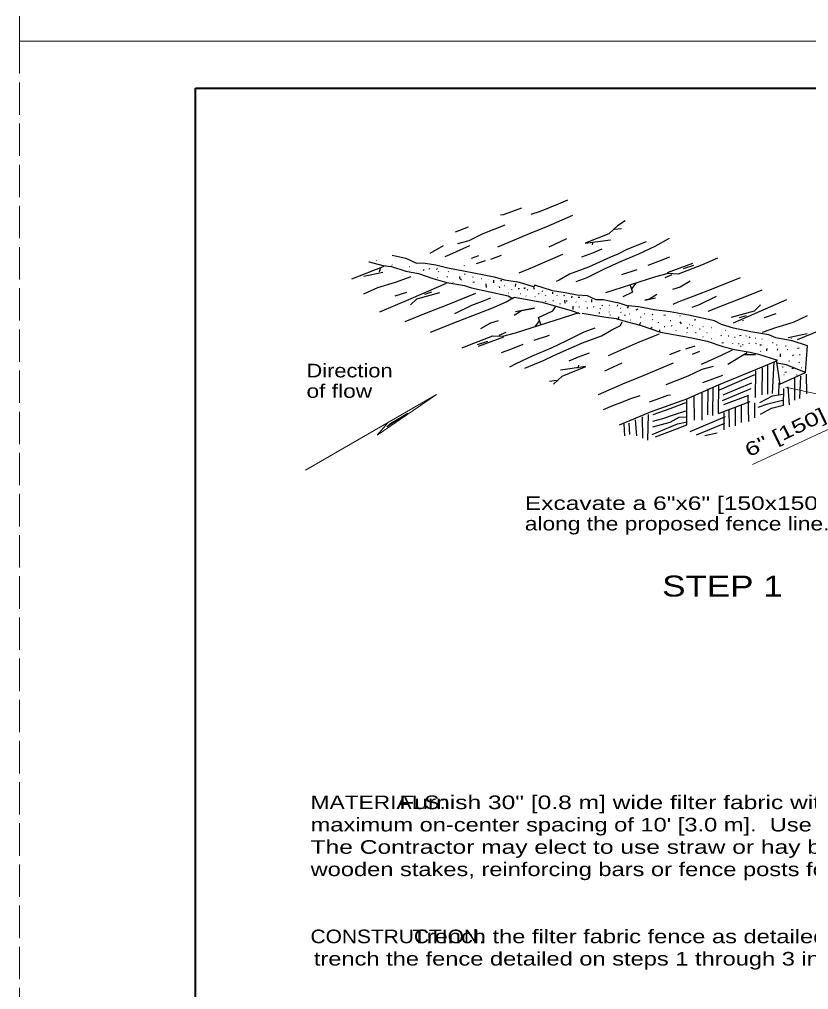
# Model space of a CAD drawing. Extents: x 1083.1 to 1117.1, y 672.5 to 716.5.
# Drawn here: x 1083.13 to 1092.18, y 683.63 to 694.76 of the extents above; entities that cross this region are included whole.
import ezdxf

# ---------------------------------------------------------------- set-up
doc = ezdxf.new("R2010")
doc.units = 0
doc.header["$LTSCALE"] = 0.062
doc.linetypes.add('LONG_DASHED', pattern=[7.5, 6, -1.5])
doc.layers.add('1', color=7, linetype='Continuous', lineweight=13)

msp = doc.modelspace()

# ---------------------------------------------------------------- linework, layer by layer
at = {"layer": '1', "lineweight": 25}
for p, q in [((1085.14617, 693.96842), (1116.64617, 693.96842)), ((1085.14617, 672.96842), (1085.14617, 693.96842)), ((1088.27583, 692.37417), (1088.12517, 692.31983)), ((1090.03117, 692.35733), (1089.95358, 692.34725)), ((1089.40017, 692.24183), (1089.198, 692.14725)), ((1089.69883, 692.17333), (1089.70692, 692.20775)), ((1087.9885, 692.16242), (1087.83625, 692.07217)), ((1087.13633, 691.97783), (1087.14017, 691.97783)), ((1087.21825, 691.98925), (1087.22358, 691.995)), ((1087.40317, 692.05483), (1087.56, 692.0205)), ((1087.98525, 691.98033), (1087.98525, 691.98242)), ((1088.39283, 692.04892), (1088.30775, 692.01483)), ((1088.47092, 691.98842), (1088.36717, 691.95633)), ((1088.65175, 692.05267), (1088.53117, 692.0035)), ((1086.941, 691.78267), (1087.30975, 691.929)), ((1087.25858, 691.8655), (1087.272, 691.91433)), ((1087.39858, 691.94333), (1087.40125, 691.9405)), ((1087.60042, 691.92325), (1087.60583, 691.92617)), ((1087.68383, 691.86875), (1087.68658, 691.86875)), ((1087.7565, 691.87733), (1087.77, 691.88883)), ((1087.91267, 691.88883), (1087.92342, 691.90317)), ((1087.938, 691.86133), (1087.93258, 691.86708)), ((1088.05267, 691.86133), (1088.04725, 691.86708)), ((1088.23025, 691.9315), (1088.2305, 691.93492)), ((1090.20925, 691.88833), (1090.03283, 691.83067)), ((1090.84667, 691.95858), (1090.55733, 691.85067)), ((1090.85917, 691.93817), (1090.74075, 691.89792)), ((1087.29358, 691.85725), (1087.07825, 691.81133)), ((1087.92733, 691.79383), (1087.92192, 691.79958)), ((1088.03667, 691.80383), (1088.03125, 691.80958)), ((1088.23933, 691.83383), (1088.23392, 691.83958)), ((1088.33258, 691.79883), (1088.32725, 691.80458)), ((1088.42133, 691.7855), (1088.42675, 691.7855)), ((1088.50208, 691.77117), (1088.50475, 691.77117)), ((1088.56942, 691.73675), (1088.56667, 691.76825)), ((1088.646, 691.76258), (1088.6595, 691.76258)), ((1090.60908, 691.83067), (1090.52917, 691.7955)), ((1088.10333, 691.73633), (1088.09792, 691.74208)), ((1088.23292, 691.708), (1088.3135, 691.6795)), ((1088.32717, 691.74533), (1088.34867, 691.74817)), ((1088.48325, 691.68508), (1088.48058, 691.72525)), ((1088.54783, 691.67358), (1088.55058, 691.67358)), ((1088.63133, 691.6965), (1088.634, 691.67933)), ((1088.6905, 691.70517), (1088.69317, 691.70517)), ((1088.77667, 691.65925), (1088.77392, 691.665)), ((1088.817, 691.6965), (1088.81967, 691.72525)), ((1088.84658, 691.67358), (1088.86275, 691.67358)), ((1088.95808, 691.654), (1088.95275, 691.65975)), ((1089.03358, 691.66208), (1089.0255, 691.68225)), ((1089.12875, 691.6365), (1089.12333, 691.64225)), ((1090.197, 691.73433), (1090.14592, 691.66833)), ((1087.43625, 691.5875), (1087.57083, 691.6305)), ((1087.85342, 691.63017), (1087.77267, 691.60433)), ((1088.73358, 691.62192), (1088.73625, 691.62475)), ((1088.8735, 691.61042), (1088.87083, 691.61042)), ((1088.93942, 691.584), (1088.93408, 691.58975)), ((1089.04433, 691.576), (1089.039, 691.576)), ((1089.08742, 691.61042), (1089.07933, 691.61042)), ((1089.16608, 691.589), (1089.16067, 691.59475)), ((1089.24625, 691.61042), (1089.2435, 691.63058)), ((1089.25158, 691.53008), (1089.2435, 691.53008)), ((1089.29942, 691.589), (1089.294, 691.59475)), ((1089.37542, 691.59033), (1089.37808, 691.60183)), ((1089.38617, 691.50425), (1089.3835, 691.53867)), ((1089.39967, 691.53008), (1089.41042, 691.533)), ((1089.55575, 691.57025), (1089.53425, 691.57025)), ((1089.693, 691.51575), (1089.693, 691.54733)), ((1090.29875, 691.53875), (1090.42325, 691.56475)), ((1089.16608, 691.5215), (1089.16067, 691.52725)), ((1089.33142, 691.4915), (1089.326, 691.49725)), ((1089.48042, 691.4325), (1089.48042, 691.46983)), ((1089.51267, 691.51575), (1089.51, 691.51858)), ((1089.54233, 691.46408), (1089.55308, 691.46408)), ((1089.62842, 691.52433), (1089.62575, 691.5215)), ((1089.63383, 691.45258), (1089.64725, 691.45258)), ((1089.70917, 691.46692), (1089.71725, 691.46408)), ((1089.814, 691.474), (1089.80858, 691.47975)), ((1089.89667, 691.4765), (1089.89125, 691.48225)), ((1090.12267, 691.46675), (1089.98267, 691.51267)), ((1089.98642, 691.46983), (1089.99183, 691.487)), ((1090.02142, 691.44683), (1090.02408, 691.44683)), ((1090.11292, 691.44683), (1090.10217, 691.46408)), ((1090.20175, 691.42967), (1090.22325, 691.44108)), ((1089.78458, 691.38658), (1089.7765, 691.39808)), ((1089.89492, 691.40092), (1089.89492, 691.40383)), ((1089.90733, 691.364), (1089.90192, 691.36967)), ((1089.99717, 691.31483), (1090.00258, 691.34925)), ((1090.03, 691.394), (1090.02458, 691.39967)), ((1090.06983, 691.37225), (1090.06717, 691.36075)), ((1090.12908, 691.378), (1090.12642, 691.378)), ((1090.13175, 691.31483), (1090.13717, 691.31483)), ((1090.25558, 691.34067), (1090.25558, 691.34642)), ((1090.29867, 691.38658), (1090.30133, 691.38658)), ((1090.3955, 691.37225), (1090.38475, 691.37508)), ((1090.39017, 691.31483), (1090.39283, 691.32058)), ((1090.51708, 691.36758), (1090.53592, 691.3705)), ((1090.71142, 691.35158), (1090.706, 691.35733)), ((1091.10083, 691.30325), (1090.80208, 691.36642)), ((1090.86642, 691.31508), (1090.88525, 691.318)), ((1091.38667, 691.33825), (1091.46742, 691.36408)), ((1091.42917, 691.30325), (1091.42883, 691.31067)), ((1091.80383, 691.38092), (1091.66933, 691.33792)), ((1089.04308, 691.23408), (1089.09425, 691.30008)), ((1090.23408, 691.24883), (1090.25558, 691.28608)), ((1090.36592, 691.21433), (1090.38475, 691.22875)), ((1090.45825, 691.2805), (1090.45825, 691.28625)), ((1090.47358, 691.17417), (1090.47358, 691.19717)), ((1090.52283, 691.23742), (1090.53092, 691.23742)), ((1090.59017, 691.30633), (1090.59825, 691.30633)), ((1090.61275, 691.23908), (1090.60733, 691.24483)), ((1090.722, 691.269), (1090.70592, 691.292)), ((1090.78392, 691.2145), (1090.792, 691.226)), ((1090.80817, 691.26042), (1090.81358, 691.26042)), ((1090.8485, 691.24317), (1090.84317, 691.24892)), ((1090.92925, 691.20875), (1090.93467, 691.20875)), ((1090.96967, 691.23458), (1090.96425, 691.23458)), ((1091.06925, 691.22025), (1091.06658, 691.22025)), ((1088.39342, 691.00983), (1088.68275, 691.11775)), ((1088.631, 691.13775), (1088.711, 691.17292)), ((1089.03083, 691.08008), (1089.20725, 691.13775)), ((1090.65742, 691.1915), (1090.65742, 691.18867)), ((1090.78608, 691.16408), (1090.78067, 691.16983)), ((1090.8835, 691.16858), (1090.88892, 691.16858)), ((1090.96967, 691.11692), (1090.96425, 691.11975)), ((1091.01542, 691.16283), (1091.01, 691.16283)), ((1091.06925, 691.09683), (1091.06658, 691.09683)), ((1091.10958, 691.16567), (1091.11233, 691.16567)), ((1091.17425, 691.137), (1091.17958, 691.12833)), ((1091.22533, 691.19442), (1091.23075, 691.19442)), ((1091.25767, 691.13125), (1091.263, 691.12833)), ((1091.32767, 691.114), (1091.33842, 691.114)), ((1091.38633, 691.13508), (1091.40517, 691.13792)), ((1091.46492, 691.12267), (1091.46225, 691.12833)), ((1091.49717, 691.11692), (1091.51067, 691.10542)), ((1091.56992, 691.10258), (1091.57525, 691.10258)), ((1091.64258, 691.09683), (1091.64792, 691.09683)), ((1091.9465, 691.11117), (1092.16183, 691.15708)), ((1091.98158, 691.10292), (1091.98067, 691.09983)), ((1092.29917, 691.18575), (1092.04742, 691.08583)), ((1088.20533, 690.99033), (1088.29, 691.02742)), ((1088.38092, 691.03025), (1088.49942, 691.0705)), ((1090.76925, 690.98), (1090.87917, 691.01408)), ((1091.18367, 691.05008), (1091.20258, 691.05292)), ((1091.30883, 691.04225), (1091.30883, 691.04517)), ((1091.3815, 691.0365), (1091.37342, 691.0365)), ((1091.40467, 691.009), (1091.39925, 691.01475)), ((1091.42183, 691.03083), (1091.42725, 691.03083)), ((1091.49183, 691.04517), (1091.50258, 691.04517)), ((1091.58067, 691.0365), (1091.57525, 691.04225)), ((1091.61833, 691.02508), (1091.63717, 691.02792)), ((1091.69908, 690.959), (1091.70442, 690.98483)), ((1091.76633, 691.05375), (1091.77175, 691.05375)), ((1091.81208, 691.02792), (1091.82017, 691.02792)), ((1091.82292, 690.97917), (1091.82017, 690.96475)), ((1091.91567, 691.01625), (1091.92108, 691.01625)), ((1092.05292, 690.99008), (1092.07175, 690.99292)), ((1090.58833, 690.91567), (1090.70892, 690.96492)), ((1090.84725, 690.9195), (1090.93242, 690.9535)), ((1091.25158, 690.806), (1091.47508, 690.93842)), ((1091.56917, 690.91292), (1091.448, 690.91292)), ((1091.63133, 690.949), (1091.62592, 690.95475)), ((1091.85792, 690.89017), (1091.85517, 690.92175)), ((1091.94058, 690.9665), (1091.93525, 690.97225)), ((1091.99508, 690.91092), (1092.00308, 690.90092)), ((1092.07567, 690.91625), (1092.08108, 690.91625)), ((1088.752, 690.7735), (1088.82383, 690.81425)), ((1089.54125, 690.79508), (1089.53317, 690.76067)), ((1089.83992, 690.72658), (1090.04208, 690.82117)), ((1091.64533, 690.45425), (1091.64883, 690.76442)), ((1091.71275, 690.46183), (1091.71275, 690.79092)), ((1091.76592, 690.46942), (1091.78367, 690.8325)), ((1091.881, 690.77367), (1091.88642, 690.77367)), ((1091.953, 690.84125), (1091.95842, 690.84125)), ((1091.98625, 690.755), (1092.00517, 690.75783)), ((1092.07392, 690.8215), (1092.0685, 690.82725)), ((1092.097, 690.76617), (1092.10242, 690.76617)), ((1090.96433, 690.59425), (1091.19483, 690.67742)), ((1091.15583, 690.511), (1091.56375, 690.685)), ((1091.57083, 690.424), (1091.57442, 690.72658)), ((1091.89433, 690.68617), (1091.89975, 690.68617)), ((1091.90633, 690.7125), (1091.92517, 690.71533)), ((1092.02075, 690.39367), (1092.02075, 690.64708)), ((1092.041, 690.68117), (1092.04642, 690.68117)), ((1092.0775, 690.41258), (1092.09167, 690.666)), ((1092.15908, 690.46558), (1092.1555, 690.68867)), ((1089.20892, 690.61108), (1089.2865, 690.62117)), ((1089.25208, 690.57508), (1089.25358, 690.576)), ((1091.08133, 690.216), (1091.08492, 690.54125)), ((1091.14517, 690.24242), (1091.14875, 690.56775)), ((1091.19842, 690.45425), (1091.52825, 690.59042)), ((1091.83683, 690.45808), (1091.84042, 690.59042)), ((1091.96042, 690.33692), (1091.94625, 690.545)), ((1090.87208, 690.163), (1090.865, 690.43917)), ((1090.95717, 690.163), (1090.95717, 690.4845)), ((1091.02458, 690.2235), (1091.02817, 690.52233)), ((1091.19133, 690.39), (1091.52117, 690.52617)), ((1091.48925, 690.44667), (1091.20192, 690.337)), ((1091.49283, 690.14792), (1091.48567, 690.44292)), ((1091.89008, 690.33325), (1091.89358, 690.52617)), ((1091.14517, 690.23867), (1091.5105, 690.37858)), ((1091.40767, 690.13658), (1091.40767, 690.337)), ((1091.56375, 690.1895), (1091.56375, 690.35967)), ((1090.27617, 689.955), (1090.27267, 690.20083)), ((1090.3365, 689.93233), (1090.34358, 690.22733)), ((1090.82242, 690.03442), (1091.22675, 690.20467)), ((1091.20908, 690.05333), (1091.20908, 690.25)), ((1091.27292, 690.08742), (1091.26933, 690.2765)), ((1091.34025, 690.09875), (1091.34025, 690.303)), ((1090.0705, 689.9815), (1090.06333, 690.12142)), ((1090.12725, 689.99658), (1090.12008, 690.129)), ((1090.20883, 689.9815), (1090.19458, 690.16683)), ((1090.89333, 689.99283), (1091.21967, 690.129)), ((1090.98917, 689.98525), (1091.131, 690.01933))]:
    msp.add_line(p, q, dxfattribs=at)
at = {"layer": '1'}
for p, q in [((1091.91592, 690.543), (1093.09275, 690.28583)), ((1091.53567, 689.65442), (1092.9485, 690.3135))]:
    msp.add_line(p, q, dxfattribs=at)
at = {"layer": '1', "linetype": 'LONG_DASHED'}
for points in [[(1083.12642, 694.50825), (1117.12642, 694.50825), (1117.12642, 716.50825), (1083.12642, 716.50825)], [(1083.12642, 672.50825), (1117.12642, 672.50825), (1117.12642, 694.50825), (1083.12642, 694.50825)]]:
    msp.add_lwpolyline(points, close=True, dxfattribs=at)
at = {"layer": '1', "lineweight": 40}
msp.add_lwpolyline([(1085.14617, 693.96842), (1116.64617, 693.96842), (1116.64617, 672.96842), (1085.14617, 672.96842)], close=True, dxfattribs=at)
at = {"layer": '1', "lineweight": 25}
for points in [[(1089.41442, 692.68433), (1089.308, 692.639), (1089.20158, 692.59733), (1089.09867, 692.55575), (1088.99225, 692.52167)], [(1088.88592, 692.59358), (1088.81142, 692.56708), (1088.67658, 692.51792), (1088.64467, 692.51417)], [(1089.47142, 692.51025), (1089.16333, 692.37733), (1089.01983, 692.31967), (1088.61058, 692.14658)], [(1090.07475, 692.44758), (1089.9865, 692.39242), (1089.88775, 692.29958), (1089.61492, 692.19175), (1089.90658, 692.23192)], [(1088.69433, 692.39692), (1088.4425, 692.29858), (1088.28292, 692.21908), (1088.15167, 692.18508)], [(1090.31583, 692.20933), (1090.09467, 692.119), (1089.99125, 692.06633), (1089.90658, 692.03125), (1089.65492, 691.91842), (1089.43617, 691.83808), (1089.31858, 691.76792), (1089.28283, 691.75108)], [(1090.57933, 692.24667), (1090.41625, 692.15417), (1090.22808, 692.06642), (1090.01167, 691.97608), (1089.83292, 691.89333), (1089.63542, 691.793), (1089.51075, 691.74783)], [(1088.29, 692.16242), (1088.05942, 692.06025), (1088.00733, 692.03483)], [(1089.80775, 692.12408), (1089.70192, 692.07892), (1089.57492, 692.03375)], [(1087.14017, 691.97783), (1087.29625, 691.93475), (1087.39583, 691.92325), (1087.55733, 691.87158), (1087.70542, 691.84292), (1087.86958, 691.78842), (1088.03108, 691.73958), (1088.23292, 691.708)], [(1087.56, 692.0205), (1087.68117, 691.96308), (1087.7565, 691.966), (1087.90183, 691.943), (1088.04183, 691.91142), (1088.22217, 691.87408), (1088.45633, 691.83108), (1088.57208, 691.80808), (1088.6905, 691.77367), (1088.8385, 691.75067)], [(1089.35758, 692.06408), (1089.01358, 691.91275), (1088.85667, 691.84875)], [(1091.13408, 692.0215), (1090.95017, 691.941), (1090.68433, 691.83817), (1090.56908, 691.84317), (1090.42325, 691.80558), (1089.848, 691.6215)], [(1090.58325, 692.03125), (1090.47742, 691.99117), (1090.33392, 691.936)], [(1087.82917, 691.90033), (1087.8265, 691.89458), (1087.82383, 691.89458)], [(1087.07558, 691.61042), (1087.23708, 691.68508), (1087.44158, 691.74533), (1087.62192, 691.8085)], [(1088.19792, 691.76825), (1088.17908, 691.78842), (1088.17908, 691.81133)], [(1090.82075, 691.75542), (1090.7055, 691.68767), (1090.6185, 691.66258)], [(1091.39575, 691.79658), (1091.08183, 691.67008), (1090.86308, 691.58483), (1090.67733, 691.51458), (1090.62117, 691.48992)], [(1088.023, 691.731), (1087.61658, 691.55592), (1087.25858, 691.40092)], [(1088.3135, 691.6795), (1088.7345, 691.58675), (1088.7815, 691.55917), (1088.80742, 691.57417), (1088.99325, 691.53908), (1089.12258, 691.5165), (1089.28017, 691.46883), (1089.45417, 691.41867), (1089.55533, 691.38608)], [(1089.24008, 691.64467), (1089.03817, 691.71067), (1089.02475, 691.69342), (1088.86325, 691.74225), (1088.82558, 691.75083)], [(1088.91392, 691.67642), (1088.92733, 691.67642), (1088.92733, 691.68217)], [(1089.98025, 691.50692), (1089.82683, 691.54417), (1089.74067, 691.54417), (1089.64383, 691.59008), (1089.52533, 691.59583), (1089.38542, 691.62167), (1089.24008, 691.6475)], [(1090.13167, 691.71025), (1090.1575, 691.63), (1090.04683, 691.577)], [(1091.6415, 691.65475), (1091.46208, 691.58183), (1091.20633, 691.48142), (1091.02192, 691.40725)], [(1087.552, 691.29467), (1087.77808, 691.38658), (1088.03375, 691.487), (1088.36217, 691.619)], [(1087.61392, 691.48417), (1087.68658, 691.55592), (1087.95033, 691.62767)], [(1087.84075, 691.17042), (1088.15825, 691.29833), (1088.377, 691.38358), (1088.56283, 691.45383), (1088.711, 691.519), (1088.78625, 691.56417)], [(1088.12058, 691.38608), (1088.31583, 691.48142), (1088.43817, 691.5265), (1088.53458, 691.56417)], [(1089.46158, 691.5645), (1089.46425, 691.56742), (1089.46692, 691.58458)], [(1090.43975, 691.60242), (1090.35508, 691.54975), (1090.30017, 691.53858)], [(1091.1195, 691.58233), (1090.92425, 691.487), (1090.84158, 691.4565)], [(1091.31667, 691.28033), (1091.6235, 691.4125), (1091.92917, 691.54483)], [(1088.80033, 691.366), (1088.885, 691.41867), (1089.03317, 691.44875), (1088.81683, 691.40367)], [(1089.1085, 691.25817), (1089.08258, 691.33842), (1089.24492, 691.41617), (1089.27542, 691.46383)], [(1089.78458, 691.444), (1089.78725, 691.444), (1089.79267, 691.444)], [(1090.41333, 691.42658), (1090.22767, 691.461), (1090.11458, 691.47533)], [(1090.80208, 691.36642), (1090.59125, 691.40417), (1090.40517, 691.42625)], [(1091.62625, 691.48425), (1091.55358, 691.4125), (1091.28975, 691.34075)], [(1088.29, 691.02742), (1088.55575, 691.13025), (1088.671, 691.12525), (1088.81683, 691.16283), (1089.54592, 691.39608)], [(1089.581, 691.3885), (1089.82925, 691.34692), (1089.97117, 691.328), (1090.04567, 691.30525), (1090.24783, 691.25233), (1090.48192, 691.17292), (1090.81892, 691.11242), (1091.0175, 691.067), (1091.19483, 691.0065), (1091.32967, 690.97242), (1091.5105, 690.94217), (1091.60633, 690.9195), (1091.82267, 690.85142)], [(1092.16458, 691.358), (1092.00308, 691.28333), (1091.7985, 691.22308), (1091.64658, 691.16992)], [(1088.41933, 691.213), (1088.53458, 691.28075), (1088.62158, 691.30583)], [(1088.82383, 690.81425), (1089.012, 690.902), (1089.22842, 690.99233), (1089.40717, 691.07508), (1089.60475, 691.17542), (1089.72942, 691.22058)], [(1088.92433, 690.75908), (1089.14542, 690.84942), (1089.24892, 690.90208), (1089.33358, 690.93717), (1089.58525, 691.05), (1089.80392, 691.13025), (1089.92158, 691.2005), (1090.02267, 691.24817), (1090.0415, 691.29083)], [(1091.17883, 691.26025), (1091.10083, 691.30325), (1091.09933, 691.30542)], [(1092.16675, 691.01408), (1091.989, 691.07367), (1091.80333, 691.10808), (1091.72258, 691.14258), (1091.518, 691.177), (1091.31617, 691.21717), (1091.17883, 691.26025)], [(1089.8825, 690.90433), (1090.2265, 691.05567), (1090.46775, 691.154)], [(1088.65692, 690.93717), (1088.76275, 690.97725), (1088.90617, 691.03242)], [(1091.8085, 690.85142), (1091.8475, 690.57533), (1092.14192, 690.70767), (1092.16675, 691.01408)], [(1089.43233, 690.84433), (1089.53817, 690.8895), (1089.66517, 690.93467)], [(1090.95008, 690.806), (1091.18067, 690.90817), (1091.30483, 690.96867)], [(1089.25358, 690.576), (1089.35233, 690.66883), (1089.62517, 690.77667), (1089.33358, 690.7365)], [(1089.76867, 690.45808), (1090.07675, 690.59108), (1090.22025, 690.64875), (1090.6295, 690.82183)], [(1090.01017, 690.11008), (1090.36483, 690.25758), (1090.78342, 690.40883), (1091.14517, 690.56775), (1091.57442, 690.7455), (1091.80142, 690.84008)], [(1090.54575, 690.5715), (1090.79758, 690.66983), (1090.95717, 690.74925), (1091.08842, 690.78333)], [(1092.14192, 690.70767), (1091.92308, 690.79833), (1091.81908, 690.81583)], [(1089.82575, 690.28408), (1089.93217, 690.32942), (1090.03858, 690.37108), (1090.14142, 690.41267), (1090.24783, 690.44667)], [(1090.35425, 690.37483), (1090.42875, 690.40133), (1090.5635, 690.4505), (1090.59542, 690.45425)], [(1091.6205, 690.36725), (1091.76592, 690.44292), (1091.87942, 690.46183)], [(1090.39675, 690.22733), (1090.59183, 690.29542), (1090.76925, 690.3635)], [(1090.42158, 689.97008), (1090.677, 690.0685), (1090.78342, 690.11008), (1090.78342, 690.40508)], [(1091.59917, 690.3105), (1091.71275, 690.34833), (1091.89358, 690.3975)], [(1091.62758, 690.23108), (1091.75175, 690.29917), (1091.89008, 690.33325)], [(1090.39325, 690.15167), (1090.50675, 690.18192), (1090.63092, 690.2235), (1090.77275, 690.26892)], [(1090.39325, 690.08742), (1090.59183, 690.14033), (1090.69475, 690.19708), (1090.77633, 690.20083)], [(1090.38617, 689.99658), (1090.677, 690.12142), (1090.78692, 690.14408)]]:
    msp.add_lwpolyline(points, dxfattribs=at)
at = {"layer": '1'}
for points in [[(1086.409, 689.58808), (1087.9125, 690.45617), (1087.23075, 689.99017), (1087.349, 690.12783)], [(1087.34225, 690.08483), (1087.58358, 690.24217), (1087.38167, 690.12558), (1087.34392, 690.09183)]]:
    msp.add_lwpolyline(points, dxfattribs=at)

# ---------------------------------------------------------------- texts
for s, height, width, p in [('Direction', 0.156, 1.2, (1086.4195, 690.65358)), ('of flow', 0.156, 1.25, (1086.4195, 690.41892)), ('Excavate a 6"x6" [150x150] trench', 0.156, 1.35, (1088.924, 689.13308)), ('along the proposed fence line.', 0.156, 1.25, (1088.924, 688.89842)), ('STEP 1', 0.24, 1.25, (1090.49942, 688.1405)), ('MATERIALS:', 0.156, 1.25, (1086.46683, 685.70267)), ('             Furnish 30" [0.8 m] wide filter fabric with sound wood supports with', 0.156, 1.35, (1086.46683, 685.70267)), ("maximum on-center spacing of 10' [3.0 m].  Use filter fabric conforming to 712.09 Type C.", 0.156, 1.3, (1086.46683, 685.44667)), ('The Contractor may elect to use straw or hay bales.  Use 30" [750] long 2"x2" [50x50]', 0.156, 1.35, (1086.46683, 685.19067)), ('wooden stakes, reinforcing bars or fence posts for the straw or hay bales.', 0.156, 1.3, (1086.46683, 684.93467)), ('CONSTRUCTION:', 0.156, 1.15, (1086.46567, 684.16525)), ('               Trench the filter fabric fence as detailed.  The Ccontractor may elect to', 0.156, 1.3, (1086.50383, 684.16525)), ('trench the fence detailed on steps 1 through 3 in one plowing operation.', 0.156, 1.3, (1086.50383, 683.90925))]:
    msp.add_text(s, height=height, dxfattribs=dict(at, width=width)).set_placement(p)
at = {"layer": '1', "width": 1.4}
msp.add_text('6" [150]', height=0.156, rotation=25.759, dxfattribs=at).set_placement((1091.495, 689.73658))

doc.saveas('drawing.dxf')
